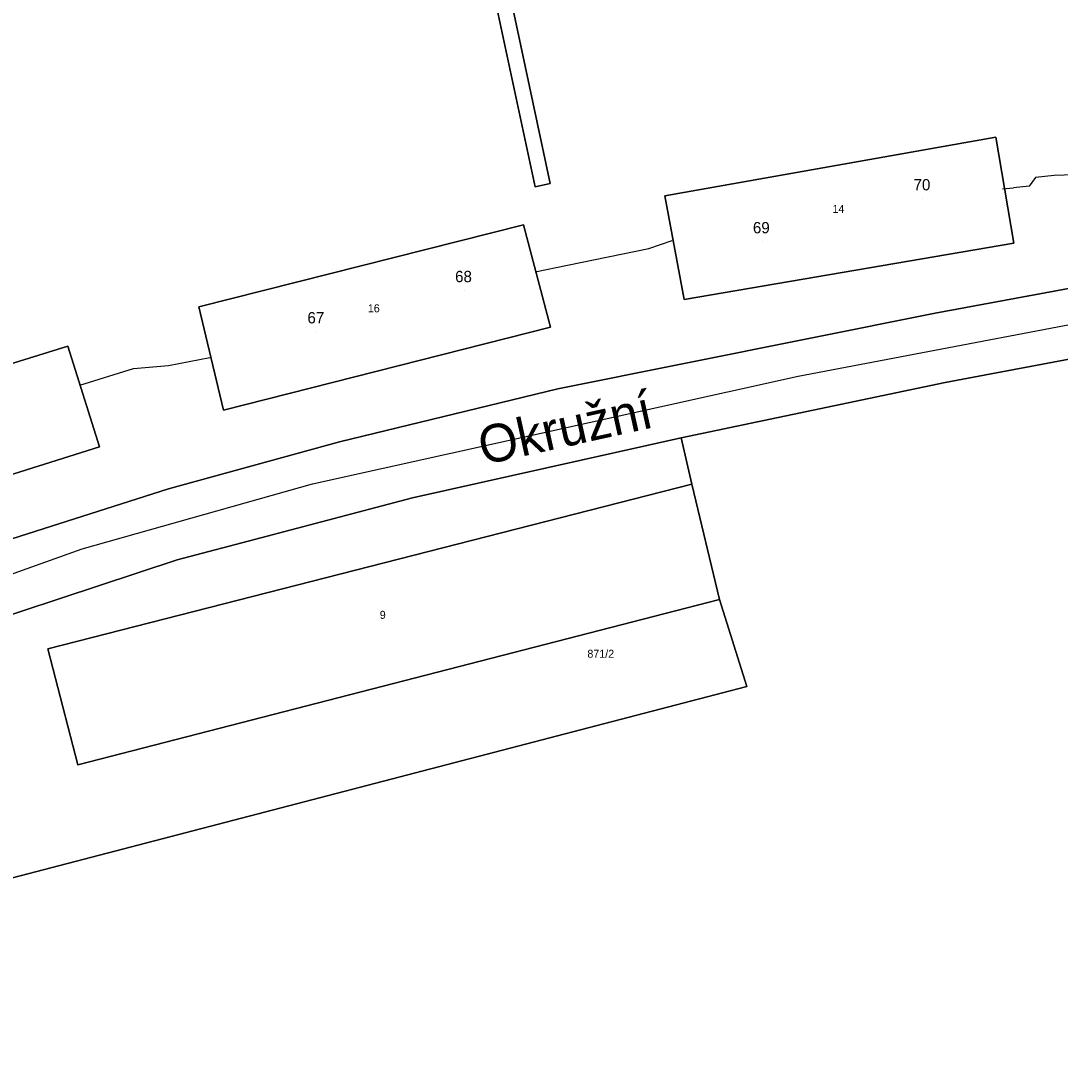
# Model space of a CAD drawing. Extents: x -873642 to -872917, y -1012962 to -1012567.
# Drawn here: x -873283.8 to -873173.4, y -1012828.2 to -1012717.8 of the extents above; entities that cross this region are included whole.
import ezdxf

# ---------------------------------------------------------------- set-up
doc = ezdxf.new("R2010")
doc.units = 0
for name, color, linetype in [('adresni_misto', 7, 'Continuous'), ('cisla_parcelni_kn', 7, 'Continuous'), ('cislo_domovni', 7, 'Continuous'), ('osy_ulic', 7, 'Continuous'), ('parcely_kn', 7, 'Continuous'), ('stavebni_objekty_bydleni', 7, 'Continuous'), ('TRASY - zamereno', 7, 'Continuous'), ('ulice', 7, 'Continuous')]:
    doc.layers.add(name, color=color, linetype=linetype)

msp = doc.modelspace()

# ---------------------------------------------------------------- linework, layer by layer
at = {"layer": 'adresni_misto'}
for p, q in [((-873187.94, -1012736.75), (-873187.94, -1012736.75)), ((-873205, -1012741.31), (-873205, -1012741.31)), ((-873236.63, -1012746.5), (-873236.63, -1012746.5)), ((-873252.31, -1012750.88), (-873252.31, -1012750.88))]:
    msp.add_line(p, q, dxfattribs=at)
at = {"layer": 'osy_ulic'}
msp.add_lwpolyline([(-873411.85, -1012822.53), (-873317.85, -1012788.44), (-873277.23, -1012773.91), (-873252.76, -1012767.01), (-873201.18, -1012755.57), (-873115.6, -1012739.3), (-873104.65, -1012731.3), (-873088.93, -1012706.26), (-873080.41, -1012681.66), (-873071.61, -1012653.78), (-873070.57, -1012650.45), (-873066.08, -1012632.13), (-873063.74, -1012625.63), (-873059.56, -1012597.3)], dxfattribs=at)
at = {"layer": 'parcely_kn'}
for points in [[(-873320.46, -1012784.28), (-873268.07, -1012767.54), (-873249.92, -1012762.57), (-873226.73, -1012756.94), (-873186.64, -1012748.89), (-873149.68, -1012742.06), (-873135.84, -1012739.52), (-873124.72, -1012736.51), (-873113.32, -1012731.6), (-873103.81, -1012724.84), (-873095.71, -1012715.02), (-873089.72, -1012704.46), (-873086.77, -1012695.86), (-873085.73, -1012692.85), (-873081.52, -1012670.94), (-873077.58, -1012656.47), (-873075.63, -1012649.79), (-873072.81, -1012640.75), (-873068.46, -1012627.76), (-873067.09, -1012621.71)], [(-873320.46, -1012784.28), (-873268.07, -1012767.54), (-873249.92, -1012762.57), (-873226.73, -1012756.94), (-873186.64, -1012748.89), (-873149.68, -1012742.06), (-873135.84, -1012739.52), (-873124.72, -1012736.51), (-873113.32, -1012731.6), (-873103.81, -1012724.84), (-873095.71, -1012715.02), (-873089.72, -1012704.46), (-873086.77, -1012695.86), (-873085.73, -1012692.85), (-873081.52, -1012670.94), (-873077.58, -1012656.47), (-873075.63, -1012649.79), (-873072.81, -1012640.75), (-873068.46, -1012627.76), (-873067.09, -1012621.71)], [(-873233.26, -1012716.13), (-873229.13, -1012735.49), (-873227.52, -1012735.13), (-873231.57, -1012716.19)], [(-873231.57, -1012716.19), (-873227.52, -1012735.13), (-873229.13, -1012735.49), (-873233.26, -1012716.13)], [(-873233.26, -1012716.13), (-873229.13, -1012735.49), (-873227.52, -1012735.13), (-873231.57, -1012716.19)], [(-873231.57, -1012716.19), (-873227.52, -1012735.13), (-873229.13, -1012735.49), (-873233.26, -1012716.13)], [(-873149.68, -1012742.06), (-873186.64, -1012748.89), (-873226.73, -1012756.94), (-873249.92, -1012762.57), (-873268.07, -1012767.54), (-873320.46, -1012784.28)], [(-873149.68, -1012742.06), (-873186.64, -1012748.89), (-873226.73, -1012756.94), (-873249.92, -1012762.57), (-873268.07, -1012767.54), (-873320.46, -1012784.28)], [(-873491.56, -1012871.97), (-873407.44, -1012826.19), (-873370.67, -1012811.62), (-873352.28, -1012804.24), (-873327.22, -1012794.59), (-873317.65, -1012791.79), (-873296.21, -1012784.7), (-873295.08, -1012789.07), (-873304.48, -1012791.83), (-873302.28, -1012798.85), (-873296.89, -1012797.13), (-873293, -1012795.88), (-873288.89, -1012809.97), (-873206.66, -1012788.54), (-873209.55, -1012779.29), (-873212.49, -1012767.05), (-873213.62, -1012762.14), (-873185.58, -1012756.25), (-873148.18, -1012749.22)], [(-873491.56, -1012871.97), (-873407.44, -1012826.19), (-873370.67, -1012811.62), (-873352.28, -1012804.24), (-873327.22, -1012794.59), (-873317.65, -1012791.79), (-873296.21, -1012784.7), (-873295.08, -1012789.07), (-873304.48, -1012791.83), (-873302.28, -1012798.85), (-873296.89, -1012797.13), (-873293, -1012795.88), (-873288.89, -1012809.97), (-873206.66, -1012788.54), (-873209.55, -1012779.29), (-873212.49, -1012767.05), (-873213.62, -1012762.14), (-873185.58, -1012756.25), (-873148.18, -1012749.22)], [(-873148.18, -1012749.22), (-873185.58, -1012756.25), (-873213.62, -1012762.14), (-873242.16, -1012768.49), (-873258.26, -1012772.76), (-873267.15, -1012775.08), (-873296.21, -1012784.7)], [(-873148.18, -1012749.22), (-873185.58, -1012756.25), (-873213.62, -1012762.14), (-873242.16, -1012768.49), (-873258.26, -1012772.76), (-873267.15, -1012775.08), (-873296.21, -1012784.7)]]:
    msp.add_lwpolyline(points, dxfattribs=at)
for points in [[(-873215.36, -1012736.42), (-873213.3, -1012747.43), (-873178.29, -1012741.46), (-873180.21, -1012730.21)], [(-873215.36, -1012736.42), (-873180.21, -1012730.21), (-873178.29, -1012741.46), (-873213.3, -1012747.43)], [(-873215.36, -1012736.42), (-873213.3, -1012747.43), (-873178.29, -1012741.46), (-873180.21, -1012730.21)], [(-873215.36, -1012736.42), (-873180.21, -1012730.21), (-873178.29, -1012741.46), (-873213.3, -1012747.43)], [(-873264.84, -1012748.21), (-873230.36, -1012739.51), (-873227.51, -1012750.39), (-873262.22, -1012759.18)], [(-873262.22, -1012759.18), (-873227.51, -1012750.39), (-873230.36, -1012739.51), (-873264.84, -1012748.21)], [(-873264.84, -1012748.21), (-873230.36, -1012739.51), (-873227.51, -1012750.39), (-873262.22, -1012759.18)], [(-873262.22, -1012759.18), (-873227.51, -1012750.39), (-873230.36, -1012739.51), (-873264.84, -1012748.21)], [(-873275.41, -1012763.1), (-873278.77, -1012752.39), (-873295.77, -1012757.66), (-873312.76, -1012762.93), (-873309.38, -1012773.75), (-873292.4, -1012768.43)], [(-873275.41, -1012763.1), (-873278.77, -1012752.39), (-873295.77, -1012757.66), (-873312.76, -1012762.93), (-873309.38, -1012773.75), (-873292.4, -1012768.43)], [(-873295.77, -1012757.66), (-873278.77, -1012752.39), (-873275.41, -1012763.1), (-873292.4, -1012768.43)], [(-873295.77, -1012757.66), (-873278.77, -1012752.39), (-873275.41, -1012763.1), (-873292.4, -1012768.43)], [(-873267.15, -1012775.08), (-873258.26, -1012772.76), (-873242.16, -1012768.49), (-873213.62, -1012762.14), (-873212.49, -1012767.05), (-873280.88, -1012784.53), (-873277.69, -1012796.87), (-873209.55, -1012779.29), (-873206.66, -1012788.54), (-873288.89, -1012809.97), (-873293, -1012795.88), (-873295.08, -1012789.07), (-873296.21, -1012784.7)], [(-873267.15, -1012775.08), (-873258.26, -1012772.76), (-873242.16, -1012768.49), (-873213.62, -1012762.14), (-873212.49, -1012767.05), (-873280.88, -1012784.53), (-873277.69, -1012796.87), (-873209.55, -1012779.29), (-873206.66, -1012788.54), (-873288.89, -1012809.97), (-873293, -1012795.88), (-873295.08, -1012789.07), (-873296.21, -1012784.7)], [(-873209.55, -1012779.29), (-873277.69, -1012796.87), (-873280.88, -1012784.53), (-873212.49, -1012767.05)], [(-873209.55, -1012779.29), (-873277.69, -1012796.87), (-873280.88, -1012784.53), (-873212.49, -1012767.05)]]:
    msp.add_lwpolyline(points, close=True, dxfattribs=at)
at = {"layer": 'stavebni_objekty_bydleni'}
for points in [[(-873215.36, -1012736.42), (-873180.21, -1012730.21), (-873178.29, -1012741.46), (-873213.3, -1012747.43)], [(-873230.36, -1012739.51), (-873227.51, -1012750.39), (-873262.22, -1012759.18), (-873264.84, -1012748.21)], [(-873312.76, -1012762.93), (-873295.77, -1012757.66), (-873278.77, -1012752.39), (-873275.41, -1012763.1), (-873292.4, -1012768.43), (-873309.38, -1012773.75)]]:
    msp.add_lwpolyline(points, close=True, dxfattribs=at)
at = {"layer": 'TRASY - zamereno'}
for p, q in [((-873175.98, -1012734.47), (-873176.65, -1012735.39)), ((-873174.01, -1012734.26), (-873175.98, -1012734.47)), ((-873170.6, -1012734.17), (-873174.01, -1012734.26)), ((-873179.48, -1012735.69), (-873178.33, -1012735.57)), ((-873176.65, -1012735.39), (-873178.33, -1012735.57)), ((-873217.07, -1012742.04), (-873214.59, -1012741.18)), ((-873225.69, -1012743.8), (-873217.07, -1012742.04)), ((-873229.13, -1012744.49), (-873225.69, -1012743.8)), ((-873268.05, -1012754.46), (-873263.68, -1012753.59)), ((-873277.47, -1012756.53), (-873271.77, -1012754.76)), ((-873271.77, -1012754.76), (-873268.05, -1012754.46))]:
    msp.add_line(p, q, dxfattribs=at)

# ---------------------------------------------------------------- texts
at = {"layer": 'cisla_parcelni_kn'}
for s, p in [('14', (-873197.55, -1012738.24)), ('14', (-873197.55, -1012738.24)), ('16', (-873246.9, -1012748.8)), ('16', (-873246.9, -1012748.8)), ('9', (-873245.63, -1012781.36)), ('9', (-873245.63, -1012781.36)), ('871/2', (-873223.58, -1012785.49)), ('871/2', (-873223.58, -1012785.49))]:
    msp.add_text(s, height=0.85, dxfattribs=at).set_placement(p)
at = {"layer": 'cislo_domovni'}
for s, p in [('70', (-873188.94, -1012735.85)), ('69', (-873206, -1012740.41)), ('68', (-873237.63, -1012745.6)), ('67', (-873253.31, -1012749.98))]:
    msp.add_text(s, height=1.2, dxfattribs=at).set_placement(p)
at = {"layer": 'ulice'}
msp.add_text('Okružní', height=4, rotation=12.5053, dxfattribs=at).set_placement((-873234.65, -1012765.04))

doc.saveas('drawing.dxf')
